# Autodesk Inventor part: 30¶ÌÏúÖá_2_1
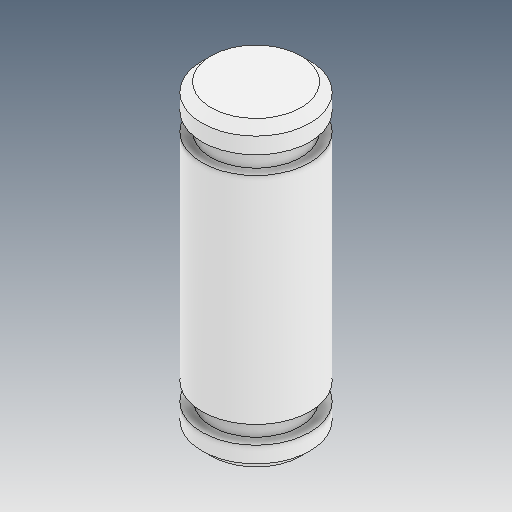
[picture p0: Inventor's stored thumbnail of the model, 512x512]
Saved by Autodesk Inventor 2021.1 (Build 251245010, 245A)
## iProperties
Created: 2021-05
Part Number: 30¶ÌÏúÖá_2_1
Material: Ogólny
Document SubType Name: Modeling
Designer: user
Density: 1 g/cm^3
Appearance: Domyślna
Author: user
Revision Number: ÈÎºÎ
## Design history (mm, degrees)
feature "ÊäÈë1"
node "Bryła1"
